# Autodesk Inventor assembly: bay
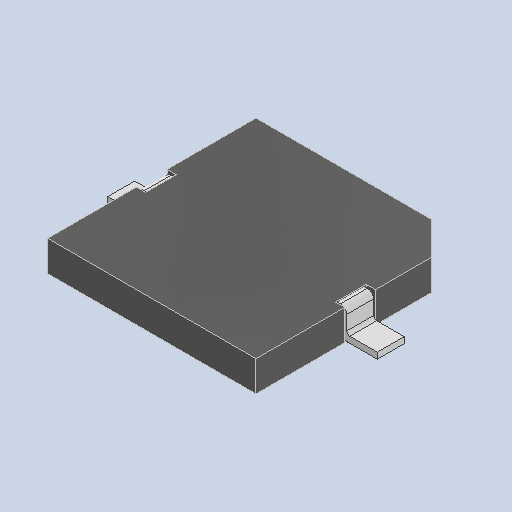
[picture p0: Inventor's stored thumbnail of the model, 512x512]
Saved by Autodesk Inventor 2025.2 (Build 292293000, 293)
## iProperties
Created: 2025-04
Part Number: bay
Description: PART--DESC
Document SubType Name: Assembly
Designer: BennF
Author: BennF
Revision Number: NONE
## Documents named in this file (3)
- C:\Users\BennF\Nextcloud\Benutzer\CNC JarBeRi\existing parts\Electronics\RepRap A4988 Shied (USE WITHOUT ARDUINO)\reprap-a4988-1.snapshot.1\RepRap\RepRap\bay_1.iam
- C:\Users\BennF\Nextcloud\Benutzer\CNC JarBeRi\existing parts\Electronics\RepRap A4988 Shied (USE WITHOUT ARDUINO)\reprap-a4988-1.snapshot.1\RepRap\RepRap\bay Geometry.ipt
- C:\Users\BennF\Nextcloud\Benutzer\CNC JarBeRi\existing parts\Electronics\RepRap A4988 Shied (USE WITHOUT ARDUINO)\reprap-a4988-1.snapshot.1\RepRap\RepRap\pin14.ipt
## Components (2 placed, 2 different names)
1. bay Geometry
2. pin14
